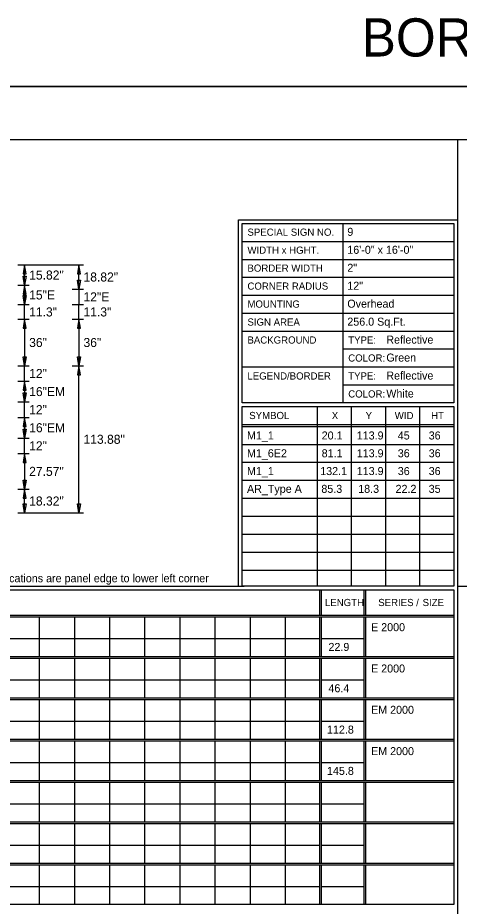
# Model space of a CAD drawing. Extents: x 2150010 to 2150174, y 145114 to 145224.
# Drawn here: x 2150048 to 2150076.4, y 145167.1 to 145224.4 of the extents above; entities that cross this region are included whole.
import ezdxf

# ---------------------------------------------------------------- set-up
doc = ezdxf.new("R2010")
doc.units = 0
for name, color, linetype in [('BORDER', 7, 'Continuous'), ('GSDIMS', 7, 'Continuous'), ('GSSHT', 7, 'Continuous'), ('Level 1', 7, 'Continuous'), ('PDF', 7, 'Continuous'), ('TEXT', 7, 'Continuous')]:
    doc.layers.add(name, color=color, linetype=linetype)

msp = doc.modelspace()

# ---------------------------------------------------------------- linework, layer by layer
at = {"layer": 'BORDER'}
for p, q in [((2150010.458, 145219.948), (2150174.061, 145219.948)), ((2150171.536, 145216.512), (2150017.557, 145216.512))]:
    msp.add_line(p, q, dxfattribs=at)
at = {"layer": 'GSDIMS'}
for p, q in [((2150047.999, 145208.445), (2150048.728, 145208.445)), ((2150047.999, 145208.445), (2150051.499, 145208.445)), ((2150048.437, 145207.127), (2150048.437, 145208.445)), ((2150051.499, 145208.445), (2150052.228, 145208.445)), ((2150051.937, 145206.877), (2150051.937, 145208.445)), ((2150047.999, 145207.127), (2150048.728, 145207.127)), ((2150047.999, 145207.127), (2150048.728, 145207.127)), ((2150048.437, 145207.127), (2150048.437, 145205.877)), ((2150051.499, 145206.877), (2150052.228, 145206.877)), ((2150051.499, 145206.877), (2150052.228, 145206.877)), ((2150051.937, 145206.877), (2150051.937, 145205.877)), ((2150047.999, 145205.877), (2150048.728, 145205.877)), ((2150047.999, 145205.877), (2150048.728, 145205.877)), ((2150048.437, 145204.935), (2150048.437, 145205.877)), ((2150051.499, 145205.877), (2150052.228, 145205.877)), ((2150051.499, 145205.877), (2150052.228, 145205.877)), ((2150051.937, 145204.935), (2150051.937, 145205.877)), ((2150047.999, 145204.935), (2150048.728, 145204.935)), ((2150047.999, 145204.935), (2150048.728, 145204.935)), ((2150048.437, 145204.935), (2150048.437, 145201.935)), ((2150051.499, 145204.935), (2150052.228, 145204.935)), ((2150051.499, 145204.935), (2150052.228, 145204.935)), ((2150051.937, 145204.935), (2150051.937, 145201.935)), ((2150047.999, 145201.935), (2150048.728, 145201.935)), ((2150047.999, 145201.935), (2150048.728, 145201.935)), ((2150048.437, 145200.935), (2150048.437, 145201.935)), ((2150051.499, 145201.935), (2150052.228, 145201.935)), ((2150051.499, 145201.935), (2150052.228, 145201.935)), ((2150051.937, 145192.445), (2150051.937, 145201.935)), ((2150047.999, 145200.935), (2150048.728, 145200.935)), ((2150047.999, 145200.935), (2150048.728, 145200.935)), ((2150048.437, 145200.935), (2150048.437, 145199.602)), ((2150047.999, 145199.602), (2150048.728, 145199.602)), ((2150047.999, 145199.602), (2150048.728, 145199.602)), ((2150048.437, 145198.602), (2150048.437, 145199.602)), ((2150047.999, 145198.602), (2150048.728, 145198.602)), ((2150047.999, 145198.602), (2150048.728, 145198.602)), ((2150048.437, 145198.602), (2150048.437, 145197.268)), ((2150047.999, 145197.268), (2150048.728, 145197.268)), ((2150047.999, 145197.268), (2150048.728, 145197.268)), ((2150048.437, 145196.268), (2150048.437, 145197.268)), ((2150047.999, 145196.268), (2150048.728, 145196.268)), ((2150047.999, 145196.268), (2150048.728, 145196.268)), ((2150048.437, 145196.268), (2150048.437, 145193.971)), ((2150047.999, 145193.971), (2150048.728, 145193.971)), ((2150047.999, 145193.971), (2150048.728, 145193.971)), ((2150048.437, 145192.445), (2150048.437, 145193.971)), ((2150047.999, 145192.445), (2150048.728, 145192.445)), ((2150047.999, 145192.445), (2150051.499, 145192.445)), ((2150051.499, 145192.445), (2150052.228, 145192.445))]:
    msp.add_line(p, q, dxfattribs=at)
for points in [[(2150048.437, 145208.445), (2150048.34, 145207.861), (2150048.534, 145207.861)], [(2150051.937, 145208.445), (2150051.84, 145207.861), (2150052.034, 145207.861)], [(2150048.437, 145207.127), (2150048.34, 145207.71), (2150048.534, 145207.71)], [(2150048.437, 145207.127), (2150048.34, 145206.543), (2150048.534, 145206.543)], [(2150051.937, 145206.877), (2150051.84, 145207.46), (2150052.034, 145207.46)], [(2150048.437, 145205.877), (2150048.34, 145206.46), (2150048.534, 145206.46)], [(2150048.437, 145204.935), (2150048.34, 145204.352), (2150048.534, 145204.352)], [(2150051.937, 145204.935), (2150051.84, 145204.352), (2150052.034, 145204.352)], [(2150048.437, 145201.935), (2150048.34, 145202.518), (2150048.534, 145202.518)], [(2150051.937, 145201.935), (2150051.84, 145202.518), (2150052.034, 145202.518)], [(2150051.937, 145201.935), (2150051.84, 145201.352), (2150052.034, 145201.352)], [(2150048.437, 145200.935), (2150048.34, 145200.352), (2150048.534, 145200.352)], [(2150048.437, 145199.602), (2150048.34, 145200.185), (2150048.534, 145200.185)], [(2150048.437, 145198.602), (2150048.34, 145198.018), (2150048.534, 145198.018)], [(2150048.437, 145197.268), (2150048.34, 145197.852), (2150048.534, 145197.852)], [(2150048.437, 145196.268), (2150048.34, 145195.685), (2150048.534, 145195.685)], [(2150048.437, 145193.971), (2150048.34, 145194.554), (2150048.534, 145194.554)], [(2150048.437, 145193.971), (2150048.34, 145193.388), (2150048.534, 145193.388)], [(2150048.437, 145192.445), (2150048.34, 145193.028), (2150048.534, 145193.028)], [(2150051.937, 145192.445), (2150051.84, 145193.028), (2150052.034, 145193.028)]]:
    msp.add_lwpolyline(points, close=True, dxfattribs=at)
at = {"layer": 'Level 1'}
for p, q in [((2150076.316, 145216.512), (2150076.316, 145117.388)), ((2150062.21, 145211.34), (2150076.316, 145211.34)), ((2150068.935, 145211.108), (2150068.935, 145199.537)), ((2150062.442, 145209.949), (2150076.084, 145209.949)), ((2150062.442, 145208.789), (2150076.084, 145208.789)), ((2150062.442, 145207.653), (2150076.084, 145207.653)), ((2150062.442, 145206.494), (2150076.084, 145206.494)), ((2150062.442, 145205.334), (2150076.084, 145205.334)), ((2150062.442, 145204.175), (2150076.084, 145204.175)), ((2150068.935, 145203.015), (2150076.084, 145203.015)), ((2150062.442, 145201.856), (2150076.084, 145201.856)), ((2150068.935, 145200.696), (2150076.084, 145200.696)), ((2150062.442, 145187.705), (2150062.442, 145199.305)), ((2150062.442, 145199.305), (2150076.084, 145199.305)), ((2150067.272, 145199.299), (2150067.272, 145198.14)), ((2150069.475, 145199.299), (2150069.475, 145198.14)), ((2150071.678, 145199.299), (2150071.678, 145198.14)), ((2150073.881, 145199.299), (2150073.881, 145198.14)), ((2150076.084, 145199.305), (2150076.084, 145187.705)), ((2150062.442, 145198.14), (2150076.084, 145198.14)), ((2150062.442, 145198.024), (2150076.084, 145198.024)), ((2150067.272, 145198.14), (2150067.272, 145187.705)), ((2150069.475, 145198.14), (2150069.475, 145187.705)), ((2150071.678, 145198.14), (2150071.678, 145187.705)), ((2150073.881, 145198.14), (2150073.881, 145187.705)), ((2150062.442, 145196.864), (2150076.084, 145196.864)), ((2150062.442, 145195.705), (2150076.084, 145195.705)), ((2150062.442, 145194.545), (2150076.084, 145194.545)), ((2150062.442, 145193.386), (2150076.084, 145193.386)), ((2150062.442, 145192.227), (2150076.084, 145192.227)), ((2150062.442, 145191.067), (2150076.084, 145191.067)), ((2150062.442, 145189.908), (2150076.084, 145189.908)), ((2150062.442, 145188.748), (2150076.084, 145188.748)), ((2150017.557, 145187.705), (2150062.583, 145187.705)), ((2150076.084, 145187.705), (2150062.442, 145187.705)), ((2150076.316, 145187.705), (2150121.342, 145187.705)), ((2150067.426, 145187.473), (2150067.426, 145185.849)), ((2150067.542, 145187.473), (2150067.542, 145185.849)), ((2150070.29, 145187.473), (2150070.29, 145185.849)), ((2150070.405, 145187.473), (2150070.405, 145185.849)), ((2150017.789, 145185.849), (2150076.084, 145185.849)), ((2150017.789, 145185.733), (2150076.084, 145185.733)), ((2150049.373, 145185.733), (2150049.373, 145183.183)), ((2150051.646, 145185.733), (2150051.646, 145183.183)), ((2150053.895, 145185.733), (2150053.895, 145183.183)), ((2150056.168, 145185.733), (2150056.168, 145183.183)), ((2150058.441, 145185.733), (2150058.441, 145183.183)), ((2150060.69, 145185.733), (2150060.69, 145183.183)), ((2150062.962, 145185.733), (2150062.962, 145183.183)), ((2150065.212, 145185.733), (2150065.212, 145183.183)), ((2150067.426, 145185.733), (2150067.426, 145183.183)), ((2150067.542, 145185.733), (2150067.542, 145183.183)), ((2150070.29, 145185.733), (2150070.29, 145183.183)), ((2150070.405, 145185.733), (2150070.405, 145183.183)), ((2150017.789, 145184.342), (2150067.426, 145184.342)), ((2150067.542, 145184.342), (2150070.29, 145184.342)), ((2150017.789, 145183.183), (2150076.084, 145183.183)), ((2150017.789, 145183.067), (2150076.084, 145183.067)), ((2150049.373, 145183.067), (2150049.373, 145180.516)), ((2150051.646, 145183.067), (2150051.646, 145180.516)), ((2150053.895, 145183.067), (2150053.895, 145180.516)), ((2150056.168, 145183.067), (2150056.168, 145180.516)), ((2150058.441, 145183.067), (2150058.441, 145180.516)), ((2150060.69, 145183.067), (2150060.69, 145180.516)), ((2150062.962, 145183.067), (2150062.962, 145180.516)), ((2150065.212, 145183.067), (2150065.212, 145180.516)), ((2150067.426, 145183.067), (2150067.426, 145180.516)), ((2150067.542, 145183.067), (2150067.542, 145180.516)), ((2150070.29, 145183.067), (2150070.29, 145180.516)), ((2150070.405, 145183.067), (2150070.405, 145180.516)), ((2150017.789, 145181.675), (2150067.426, 145181.675)), ((2150067.542, 145181.675), (2150070.29, 145181.675)), ((2150017.789, 145180.516), (2150076.084, 145180.516)), ((2150017.789, 145180.4), (2150076.084, 145180.4)), ((2150049.373, 145180.4), (2150049.373, 145177.849)), ((2150051.646, 145180.4), (2150051.646, 145177.849)), ((2150053.895, 145180.4), (2150053.895, 145177.849)), ((2150056.168, 145180.4), (2150056.168, 145177.849)), ((2150058.441, 145180.4), (2150058.441, 145177.849)), ((2150060.69, 145180.4), (2150060.69, 145177.849)), ((2150062.962, 145180.4), (2150062.962, 145177.849)), ((2150065.212, 145180.4), (2150065.212, 145177.849)), ((2150067.426, 145180.4), (2150067.426, 145177.849)), ((2150067.542, 145180.4), (2150067.542, 145177.849)), ((2150070.29, 145180.4), (2150070.29, 145177.849)), ((2150070.405, 145180.4), (2150070.405, 145177.849)), ((2150017.789, 145179.008), (2150067.426, 145179.008)), ((2150067.542, 145179.008), (2150070.29, 145179.008)), ((2150017.789, 145177.849), (2150076.084, 145177.849)), ((2150017.789, 145177.733), (2150076.084, 145177.733)), ((2150049.373, 145177.733), (2150049.373, 145175.182)), ((2150051.646, 145177.733), (2150051.646, 145175.182)), ((2150053.895, 145177.733), (2150053.895, 145175.182)), ((2150056.168, 145177.733), (2150056.168, 145175.182)), ((2150058.441, 145177.733), (2150058.441, 145175.182)), ((2150060.69, 145177.733), (2150060.69, 145175.182)), ((2150062.962, 145177.733), (2150062.962, 145175.182)), ((2150065.212, 145177.733), (2150065.212, 145175.182)), ((2150067.426, 145177.733), (2150067.426, 145175.182)), ((2150067.542, 145177.733), (2150067.542, 145175.182)), ((2150070.29, 145177.733), (2150070.29, 145175.182)), ((2150070.405, 145177.733), (2150070.405, 145175.182)), ((2150017.789, 145176.342), (2150067.426, 145176.342)), ((2150067.542, 145176.342), (2150070.29, 145176.342)), ((2150017.789, 145175.182), (2150076.084, 145175.182)), ((2150017.789, 145175.066), (2150076.084, 145175.066)), ((2150049.373, 145175.066), (2150049.373, 145172.515)), ((2150051.646, 145175.066), (2150051.646, 145172.515)), ((2150053.895, 145175.066), (2150053.895, 145172.515)), ((2150056.168, 145175.066), (2150056.168, 145172.515)), ((2150058.441, 145175.066), (2150058.441, 145172.515)), ((2150060.69, 145175.066), (2150060.69, 145172.515)), ((2150062.962, 145175.066), (2150062.962, 145172.515)), ((2150065.212, 145175.066), (2150065.212, 145172.515)), ((2150067.426, 145175.066), (2150067.426, 145172.515)), ((2150067.542, 145175.066), (2150067.542, 145172.515)), ((2150070.29, 145175.066), (2150070.29, 145172.515)), ((2150070.405, 145175.066), (2150070.405, 145172.515)), ((2150017.789, 145173.675), (2150067.426, 145173.675)), ((2150067.542, 145173.675), (2150070.29, 145173.675)), ((2150017.789, 145172.515), (2150076.084, 145172.515)), ((2150017.789, 145172.399), (2150076.084, 145172.399)), ((2150049.373, 145172.399), (2150049.373, 145169.849)), ((2150051.646, 145172.399), (2150051.646, 145169.849)), ((2150053.895, 145172.399), (2150053.895, 145169.849)), ((2150056.168, 145172.399), (2150056.168, 145169.849)), ((2150058.441, 145172.399), (2150058.441, 145169.849)), ((2150060.69, 145172.399), (2150060.69, 145169.849)), ((2150062.962, 145172.399), (2150062.962, 145169.849)), ((2150065.212, 145172.399), (2150065.212, 145169.849)), ((2150067.426, 145172.399), (2150067.426, 145169.849)), ((2150067.542, 145172.399), (2150067.542, 145169.849)), ((2150070.29, 145172.399), (2150070.29, 145169.849)), ((2150070.405, 145172.399), (2150070.405, 145169.849)), ((2150017.789, 145171.008), (2150067.426, 145171.008)), ((2150067.542, 145171.008), (2150070.29, 145171.008)), ((2150017.789, 145169.849), (2150076.084, 145169.849)), ((2150017.789, 145169.733), (2150076.084, 145169.733)), ((2150049.373, 145169.733), (2150049.373, 145167.182)), ((2150051.646, 145169.733), (2150051.646, 145167.182)), ((2150053.895, 145169.733), (2150053.895, 145167.182)), ((2150056.168, 145169.733), (2150056.168, 145167.182)), ((2150058.441, 145169.733), (2150058.441, 145167.182)), ((2150060.69, 145169.733), (2150060.69, 145167.182)), ((2150062.962, 145169.733), (2150062.962, 145167.182)), ((2150065.212, 145169.733), (2150065.212, 145167.182)), ((2150067.426, 145169.733), (2150067.426, 145167.182)), ((2150067.542, 145169.733), (2150067.542, 145167.182)), ((2150070.29, 145169.733), (2150070.29, 145167.182)), ((2150070.405, 145169.733), (2150070.405, 145167.182)), ((2150017.789, 145168.341), (2150067.426, 145168.341)), ((2150067.542, 145168.341), (2150070.29, 145168.341))]:
    msp.add_line(p, q, dxfattribs=at)
msp.add_lwpolyline([(2150062.21, 145187.705), (2150062.21, 145211.34)], dxfattribs=at)
for points in [[(2150062.442, 145211.108), (2150076.084, 145211.108), (2150076.084, 145199.537), (2150062.442, 145199.537)], [(2150017.789, 145187.473), (2150076.084, 145187.473), (2150076.084, 145167.182), (2150017.789, 145167.182)]]:
    msp.add_lwpolyline(points, close=True, dxfattribs=at)
at = {"layer": 'PDF'}
msp.add_lwpolyline([(2150010.458, 145114.088), (2150174.061, 145114.088), (2150174.061, 145219.948), (2150010.458, 145219.948)], close=True, dxfattribs=at)

# ---------------------------------------------------------------- texts
at = {"layer": 'GSDIMS'}
for s, p in [('15.82"', (2150048.728, 145207.494)), ('18.82"', (2150052.228, 145207.369)), ('15"E', (2150048.728, 145206.21)), ('12"E', (2150052.228, 145206.085)), ('11.3"', (2150048.728, 145205.114)), ('11.3"', (2150052.228, 145205.114)), ('36"', (2150048.728, 145203.143)), ('36"', (2150052.228, 145203.143)), ('12"', (2150048.728, 145201.143)), ('16"EM', (2150048.728, 145199.977)), ('12"', (2150048.728, 145198.81)), ('16"EM', (2150048.728, 145197.643)), ('113.88"', (2150052.228, 145196.898)), ('12"', (2150048.728, 145196.477)), ('27.57"', (2150048.728, 145194.828)), ('18.32"', (2150048.728, 145192.916))]:
    msp.add_text(s, height=0.5833, dxfattribs=at).set_placement(p)
at = {"layer": 'GSSHT'}
for s, height, p in [('9', 0.517, (2150069.224, 145210.315)), ('Overhead', 0.5165, (2150069.224, 145205.679))]:
    msp.add_text(s, height=height, dxfattribs=at).set_placement(p)
at = {"layer": 'Level 1'}
for s, height, p in [('SPECIAL SIGN NO.', 0.46374, (2150062.79, 145210.32)), ('WIDTH x HGHT.', 0.46374, (2150062.79, 145209.16)), ('16\'-0" x 16\'-0"', 0.51652, (2150069.224, 145209.156)), ('BORDER WIDTH', 0.46374, (2150062.79, 145208.001)), ('2"', 0.5165, (2150069.224, 145207.997)), ('CORNER RADIUS', 0.46374, (2150062.79, 145206.841)), ('12"', 0.5165, (2150069.224, 145206.838)), ('MOUNTING', 0.4637, (2150062.79, 145205.682)), ('SIGN AREA', 0.4638, (2150062.79, 145204.522)), ('256.0 Sq.Ft.', 0.51652, (2150069.224, 145204.52)), ('BACKGROUND', 0.4637, (2150062.79, 145203.363)), ('TYPE:', 0.4637, (2150069.283, 145203.363)), ('Reflective', 0.5165, (2150071.736, 145203.361)), ('COLOR:', 0.4637, (2150069.283, 145202.203)), ('Green', 0.5165, (2150071.736, 145202.203)), ('LEGEND/BORDER', 0.46374, (2150062.79, 145201.044)), ('TYPE:', 0.4637, (2150069.283, 145201.044)), ('Reflective', 0.5165, (2150071.736, 145201.044)), ('COLOR:', 0.4637, (2150069.283, 145199.885)), ('White', 0.5165, (2150071.736, 145199.885)), ('SYMBOL', 0.4637, (2150062.906, 145198.493)), ('X', 0.464, (2150068.223, 145198.488)), ('Y', 0.464, (2150070.403, 145198.488)), ('WID', 0.4637, (2150072.281, 145198.488)), ('HT', 0.4637, (2150074.623, 145198.488)), ('M1_1', 0.5165, (2150062.761, 145197.177)), ('20.1', 0.5165, (2150067.572, 145197.177)), ('113.9', 0.5165, (2150069.831, 145197.177)), ('45', 0.5165, (2150072.474, 145197.177)), ('36', 0.5165, (2150074.467, 145197.177)), ('M1_6E2', 0.5165, (2150062.761, 145196.03)), ('81.1', 0.5165, (2150067.572, 145196.03)), ('113.9', 0.5165, (2150069.831, 145196.03)), ('36', 0.5165, (2150072.474, 145196.03)), ('36', 0.5165, (2150074.467, 145196.03)), ('M1_1', 0.5165, (2150062.761, 145194.882)), ('132.1', 0.5165, (2150067.478, 145194.882)), ('113.9', 0.5165, (2150069.831, 145194.882)), ('36', 0.5165, (2150072.474, 145194.882)), ('36', 0.5165, (2150074.467, 145194.882)), ('AR_Type A', 0.5165, (2150062.761, 145193.734)), ('85.3', 0.5165, (2150067.551, 145193.734)), ('18.3', 0.5165, (2150069.925, 145193.734)), ('22.2', 0.5165, (2150072.333, 145193.734)), ('35', 0.5165, (2150074.467, 145193.734)), ('Letter locations are panel edge to lower left corner', 0.51652, (2150044.943, 145187.968)), ('LENGTH', 0.4638, (2150067.783, 145186.429)), ('LENGTH', 0.4638, (2150067.783, 145186.429)), ('SERIES /', 0.4638, (2150071.216, 145186.429)), ('SIZE', 0.4638, (2150074.074, 145186.429)), ('E 2000', 0.5165, (2150070.753, 145184.81)), ('22.9', 0.5165, (2150068.009, 145183.535)), ('E 2000', 0.5165, (2150070.753, 145182.145)), ('46.4', 0.5165, (2150068.007, 145180.87)), ('EM 2000', 0.5165, (2150070.753, 145179.479)), ('112.8', 0.5165, (2150067.915, 145178.204)), ('EM 2000', 0.5165, (2150070.753, 145176.814)), ('145.8', 0.5165, (2150067.915, 145175.539))]:
    msp.add_text(s, height=height, dxfattribs=at).set_placement(p)
at = {"layer": 'TEXT'}
msp.add_text('BORDER AND REPORT 70 SCALE', height=2.46401, dxfattribs=at).set_placement((2150070.157, 145221.883))

doc.saveas('drawing.dxf')
